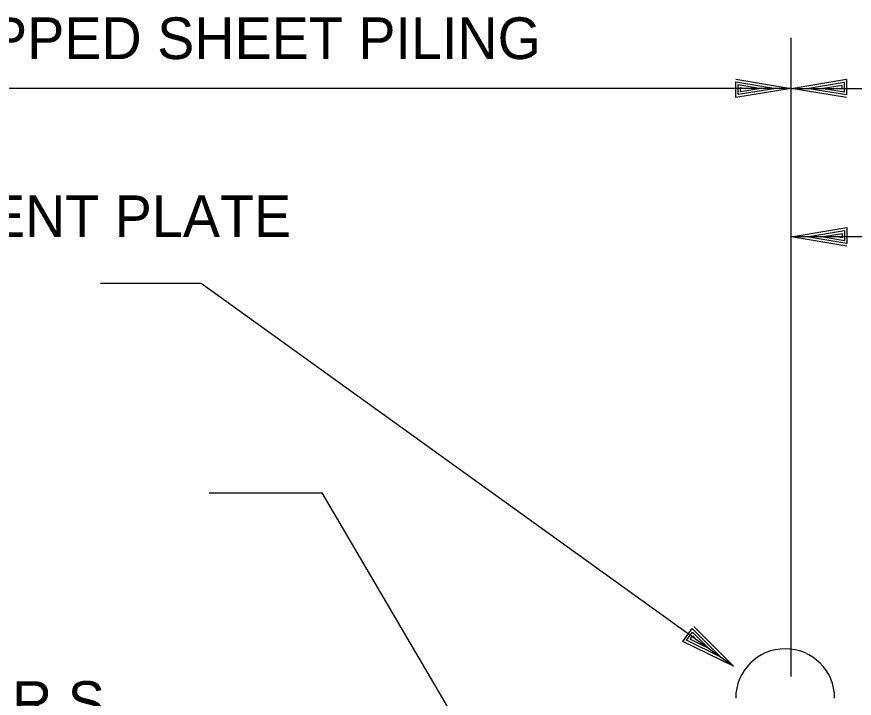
# Model space of a CAD drawing. Extents: x 22369.6 to 22428.3, y 22369.6 to 22415.
# Drawn here: x 22401.287 to 22405.041, y 22385.725 to 22388.779 of the extents above; entities that cross this region are included whole.
import ezdxf

# ---------------------------------------------------------------- set-up
doc = ezdxf.new("R2010")
doc.units = 0
for name, color, linetype in [('Level 1', 7, 'Continuous'), ('Level 10', 7, 'Continuous'), ('Level 4', 7, 'Continuous')]:
    doc.layers.add(name, color=color, linetype=linetype)

msp = doc.modelspace()

# ---------------------------------------------------------------- linework, layer by layer
at = {"layer": 'Level 1'}
for p, q in [((22404.7592, 22385.8232), (22404.7592, 22388.685)), ((22404.7592, 22388.4579), (22399.0915, 22388.4579)), ((22404.6901, 22388.4579), (22404.6901, 22388.4579)), ((22404.7592, 22388.4579), (22409.9247, 22388.4579)), ((22404.7592, 22388.4579), (22404.7592, 22388.4579)), ((22404.7592, 22388.4579), (22404.7592, 22388.4579)), ((22404.828, 22388.4579), (22404.828, 22388.4579)), ((22406.3109, 22387.7929), (22404.7592, 22387.7929)), ((22404.7592, 22387.7929), (22404.7592, 22387.7929)), ((22404.8284, 22387.7929), (22404.8284, 22387.7929)), ((22401.6622, 22387.5851), (22402.1142, 22387.5851)), ((22402.1142, 22387.5851), (22404.4993, 22385.8684)), ((22402.1498, 22386.6455), (22402.6561, 22386.6455)), ((22404.1866, 22384.0421), (22402.6561, 22386.6455)), ((22404.4432, 22385.9088), (22404.4432, 22385.9088)), ((22404.4993, 22385.8684), (22404.4993, 22385.8684))]:
    msp.add_line(p, q, dxfattribs=at)
for points in [[(22404.5105, 22388.4991), (22404.7592, 22388.4579), (22404.5105, 22388.4166), (22404.5105, 22388.4871), (22404.6901, 22388.4579), (22404.5212, 22388.4299), (22404.5212, 22388.4751), (22404.6236, 22388.4579), (22404.5318, 22388.4432), (22404.5318, 22388.4618), (22404.5544, 22388.4579)], [(22405.0067, 22388.4168), (22404.7592, 22388.4579), (22405.0067, 22388.4989), (22405.0067, 22388.4287), (22404.828, 22388.4579), (22404.9961, 22388.4856), (22404.9961, 22388.4407), (22404.8942, 22388.4579), (22404.9855, 22388.4724), (22404.9855, 22388.4539), (22404.963, 22388.4579)], [(22405.0079, 22387.7516), (22404.7592, 22387.7929), (22405.0079, 22387.8341), (22405.0079, 22387.7636), (22404.8284, 22387.7929), (22404.9973, 22387.8208), (22404.9973, 22387.7756), (22404.8949, 22387.7929), (22404.9867, 22387.8075), (22404.9867, 22387.7889), (22404.964, 22387.7929)], [(22404.3215, 22386.0472), (22404.4993, 22385.8684), (22404.2733, 22385.9803), (22404.3145, 22386.0375), (22404.4432, 22385.9088), (22404.2897, 22385.9848), (22404.3162, 22386.0216), (22404.3892, 22385.9477), (22404.3061, 22385.9894), (22404.317, 22386.0046), (22404.3331, 22385.9881)]]:
    msp.add_lwpolyline(points, dxfattribs=at)
at = {"layer": 'Level 10'}
msp.add_arc((22404.7317, 22385.7253), 0.2217, 0, 180, dxfattribs=at)

# ---------------------------------------------------------------- texts
at = {"layer": 'Level 4'}
for s, p in [('UNCAPPED SHEET PILING', (22400.4601, 22388.5894)), ('REMOVE THIS PORTION OF BENT PLATE', (22397.5791, 22387.7917)), ('W/ CONT.  SEAL RETAINING BAR, C.R.S.', (22396.9383, 22385.6149))]:
    msp.add_text(s, height=0.186698, dxfattribs=at).set_placement(p)

doc.saveas('drawing.dxf')
